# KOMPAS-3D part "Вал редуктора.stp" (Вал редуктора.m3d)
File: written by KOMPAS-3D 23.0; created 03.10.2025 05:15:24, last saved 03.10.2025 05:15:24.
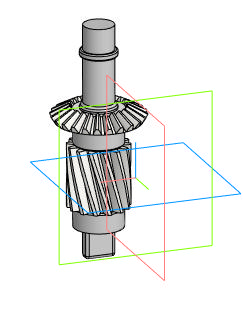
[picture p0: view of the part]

Document properties: Автор: Lost; Полное имя файла: C:\Users\Lost\Downloads\Telegram Desktop\ИМ-ИТ ЦД\ИМ-ИТ ЦД\Вариант 12\Вал редуктора.stp_1.m3d

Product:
- Part/product: Вал редуктора.stp

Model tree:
1. Операция без истории:1

Referenced files: Вал редуктора.stp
